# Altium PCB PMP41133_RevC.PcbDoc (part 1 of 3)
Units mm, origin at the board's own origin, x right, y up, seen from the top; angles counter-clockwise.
Board outline 150 x 82 mm, 4 copper layers (Top Layer, Int1 (GND), Int2 (PWR), Bottom Layer), stack 1.369 mm thick; 186 components, 74 nets, 388 pads, 329 vias.
Unrouted connection lines stored in the file: 2.
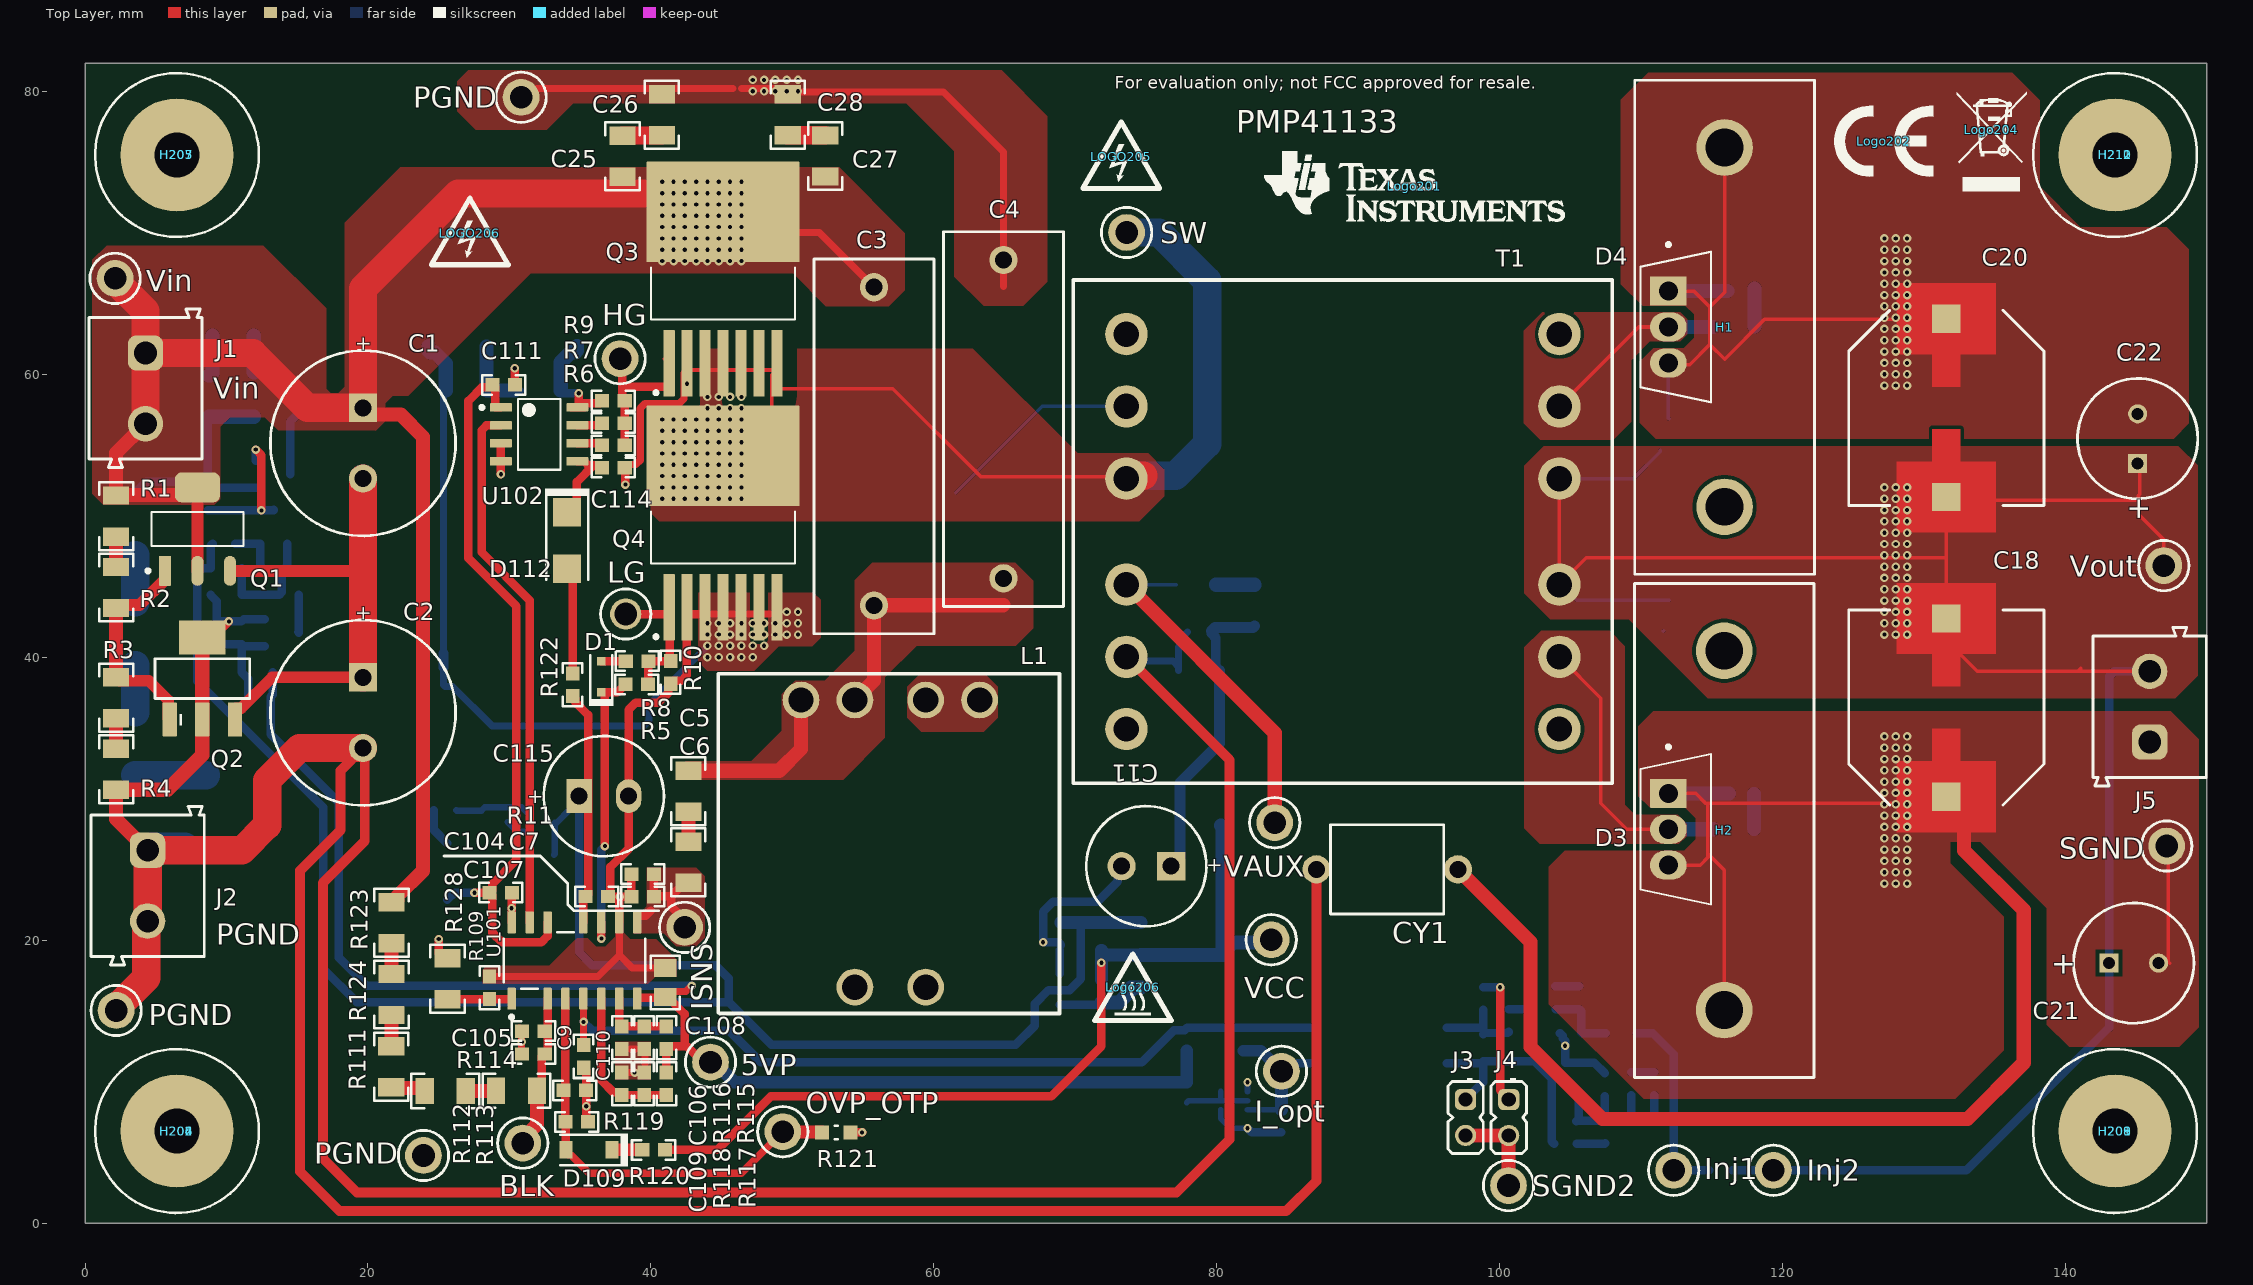
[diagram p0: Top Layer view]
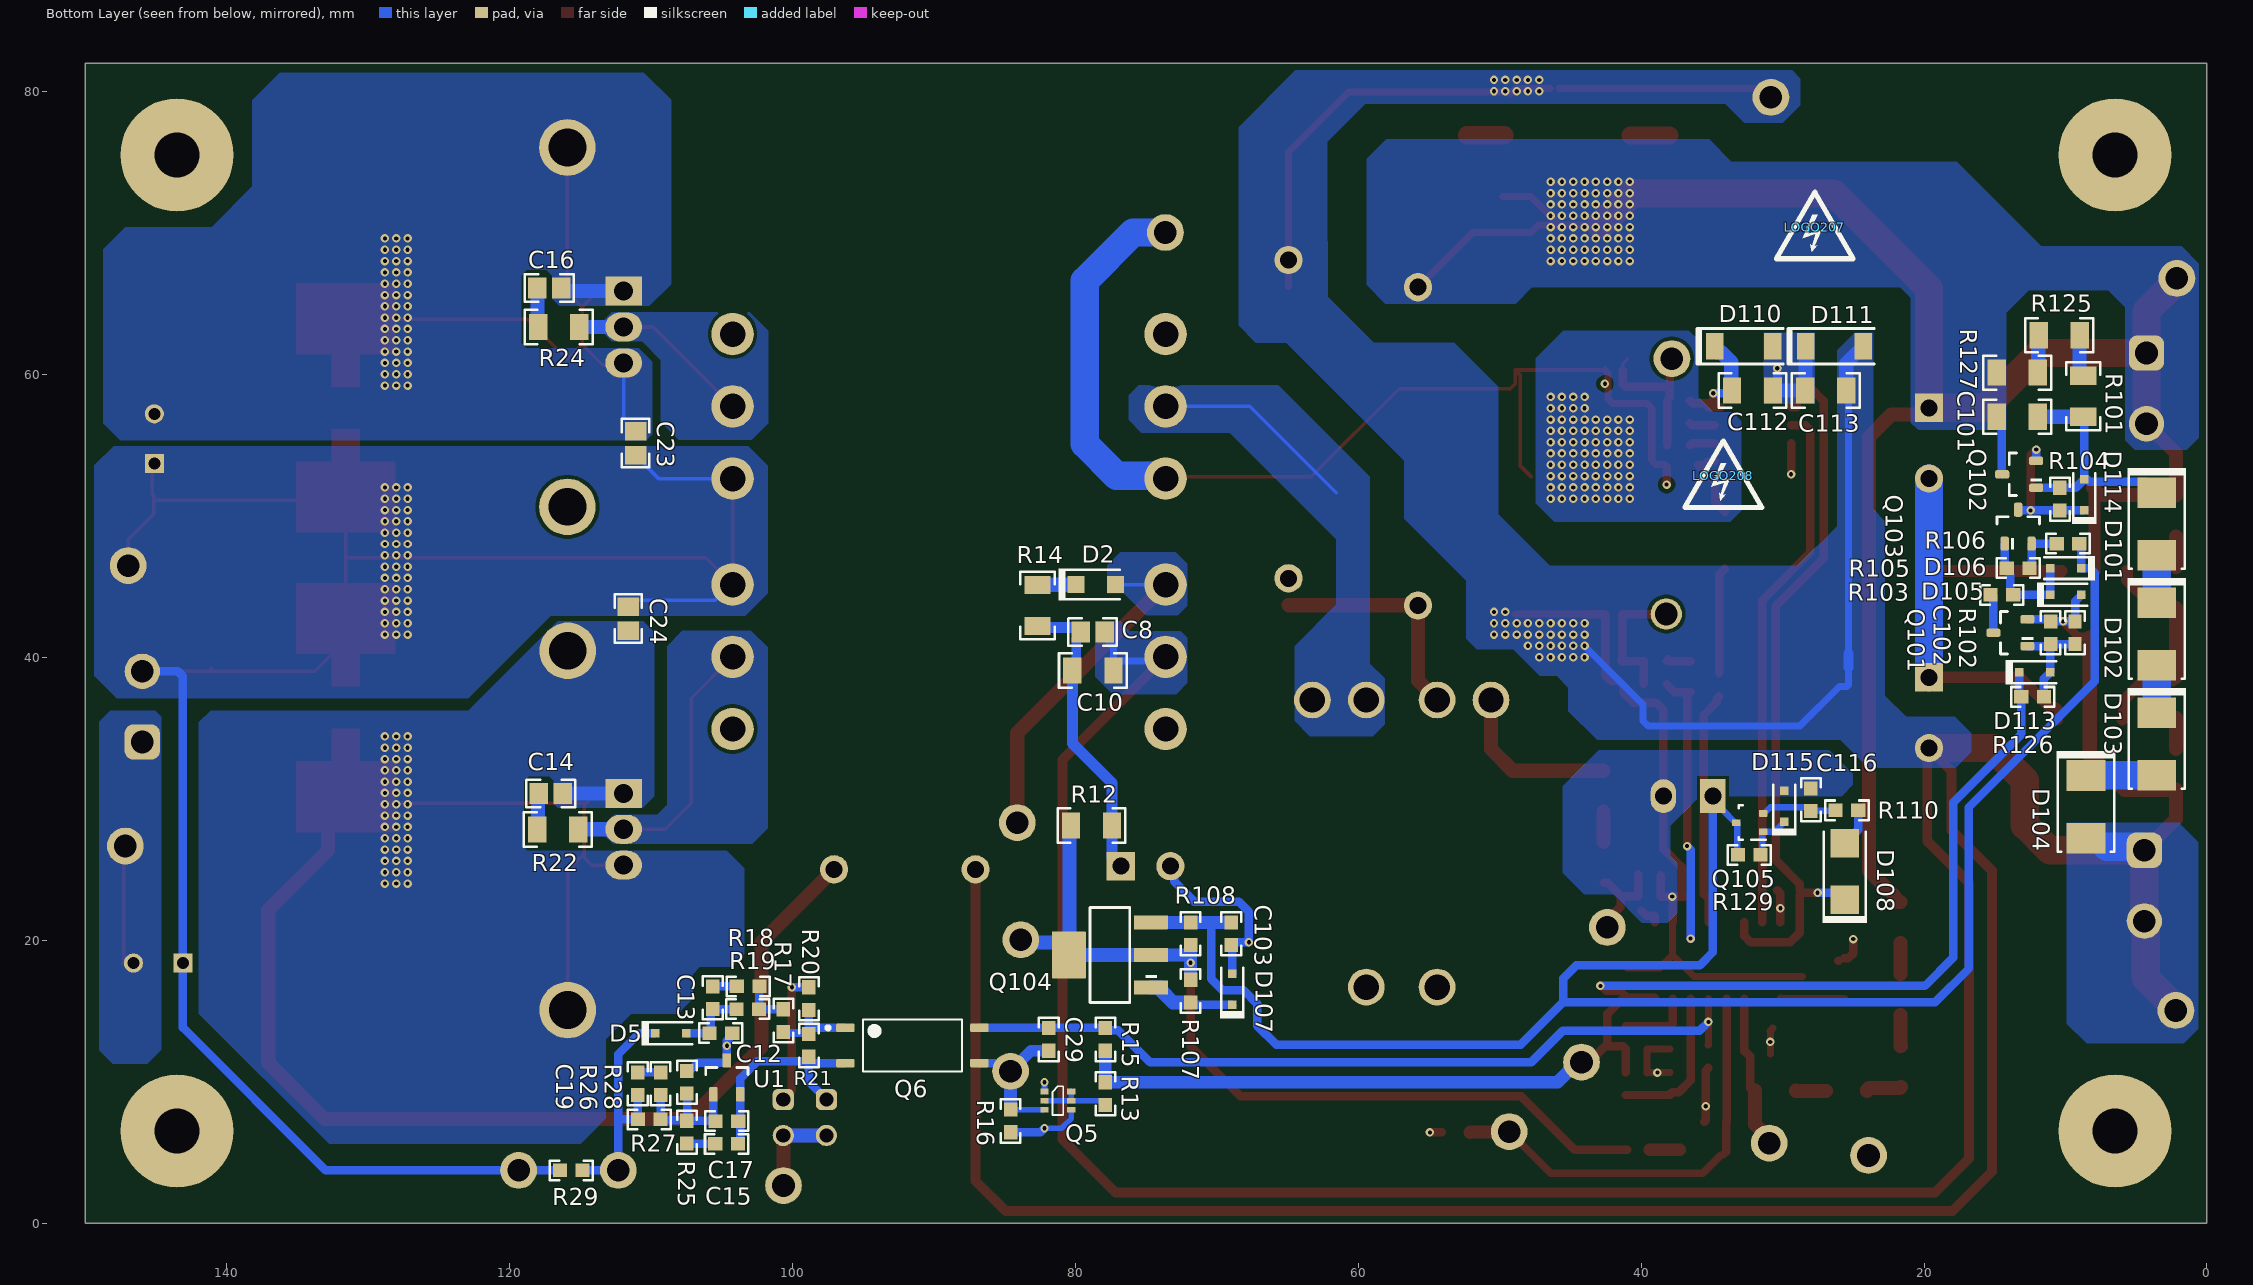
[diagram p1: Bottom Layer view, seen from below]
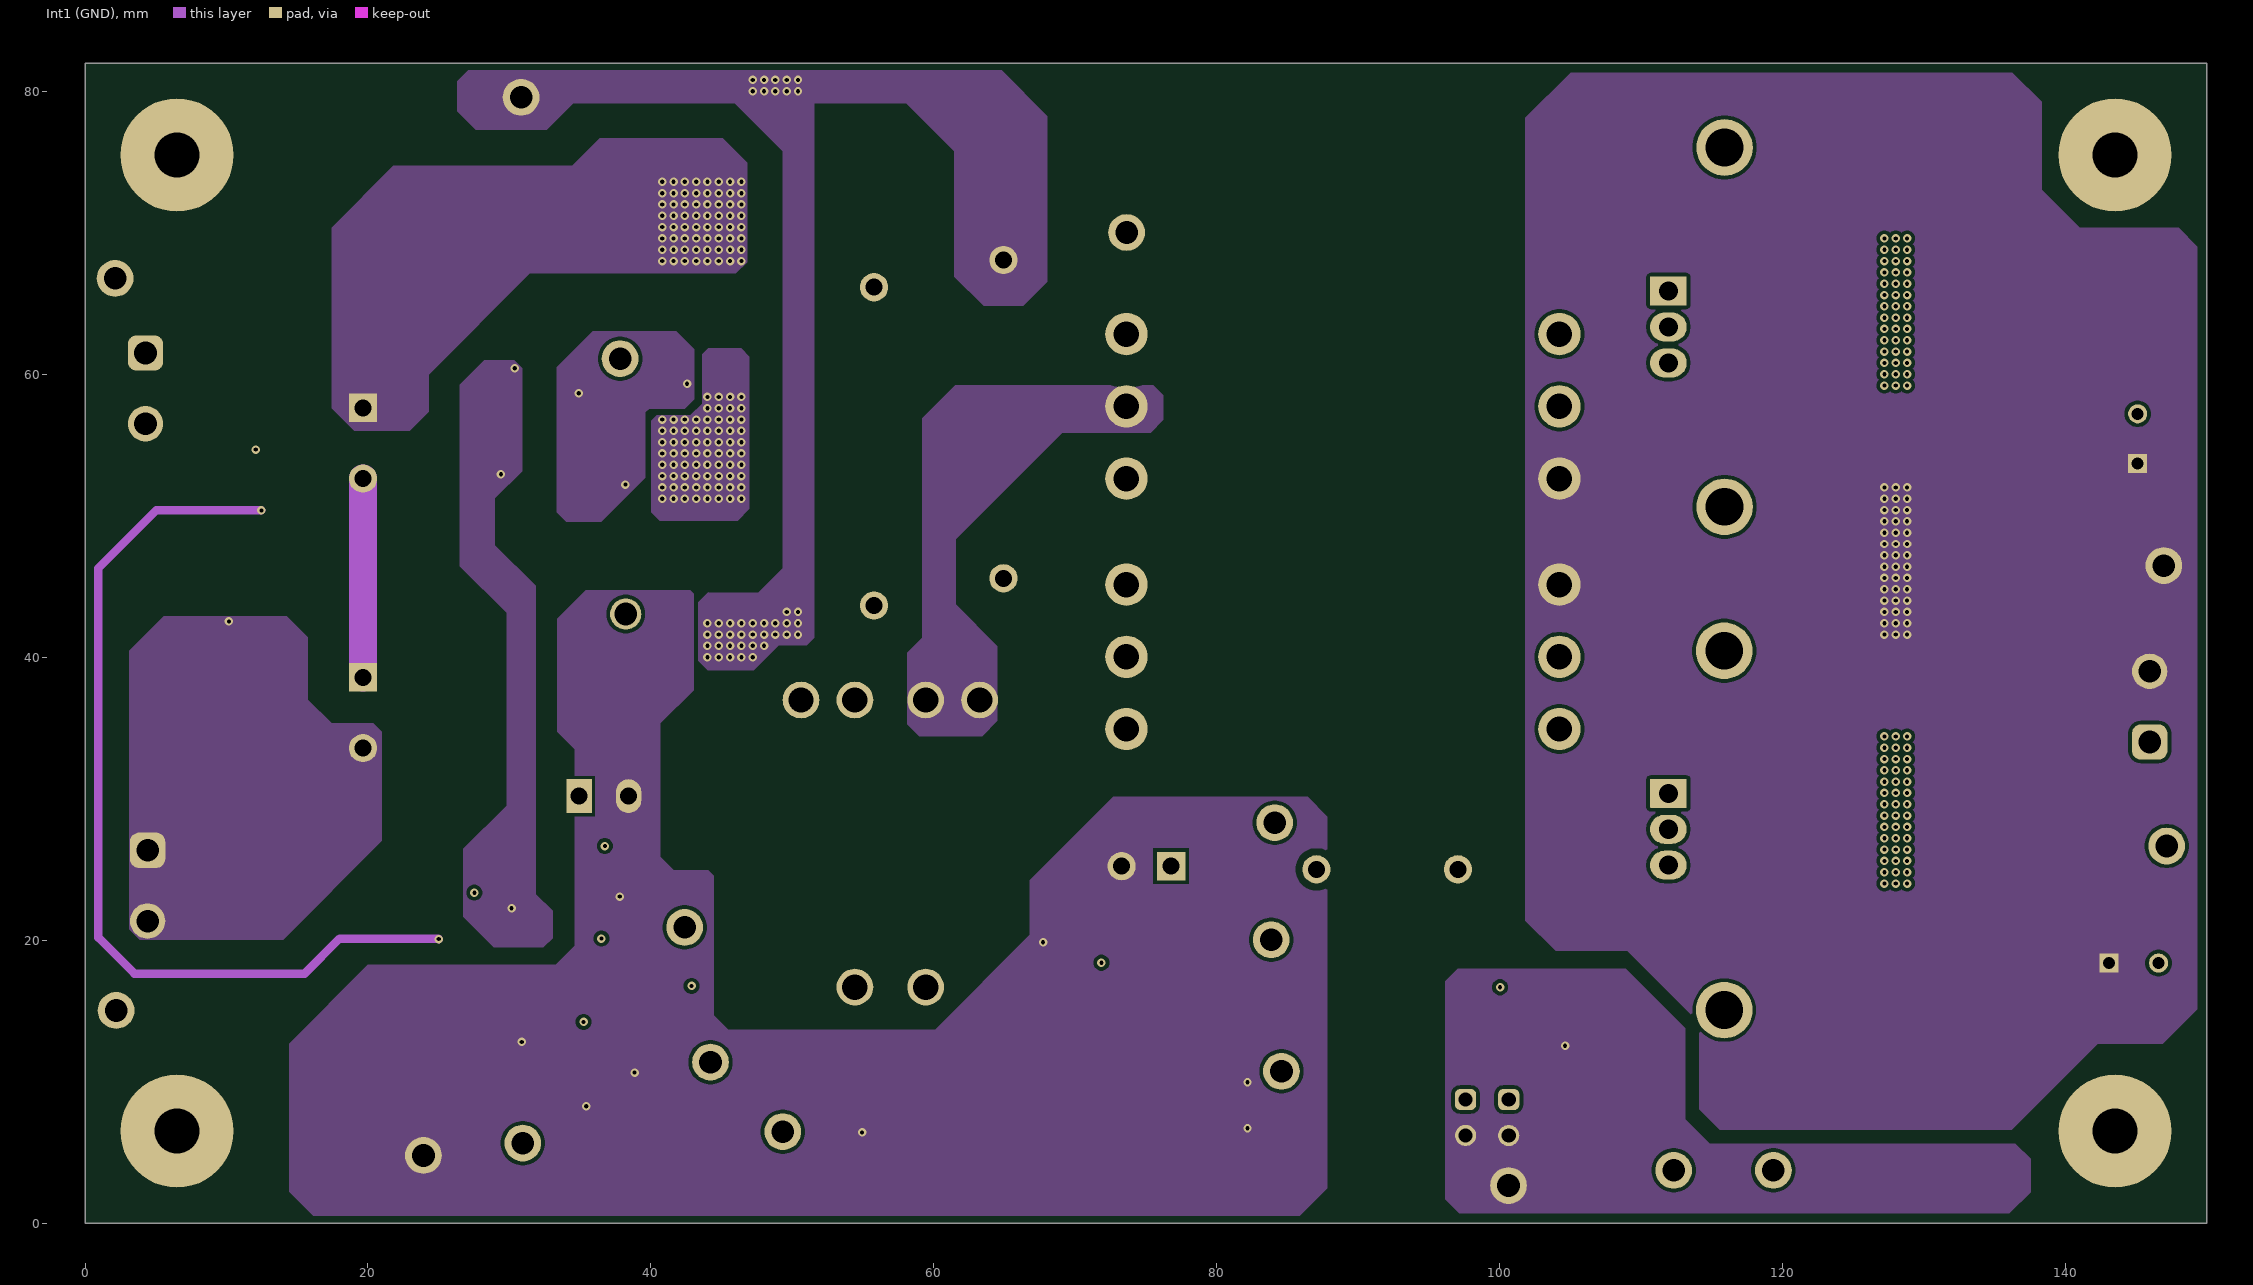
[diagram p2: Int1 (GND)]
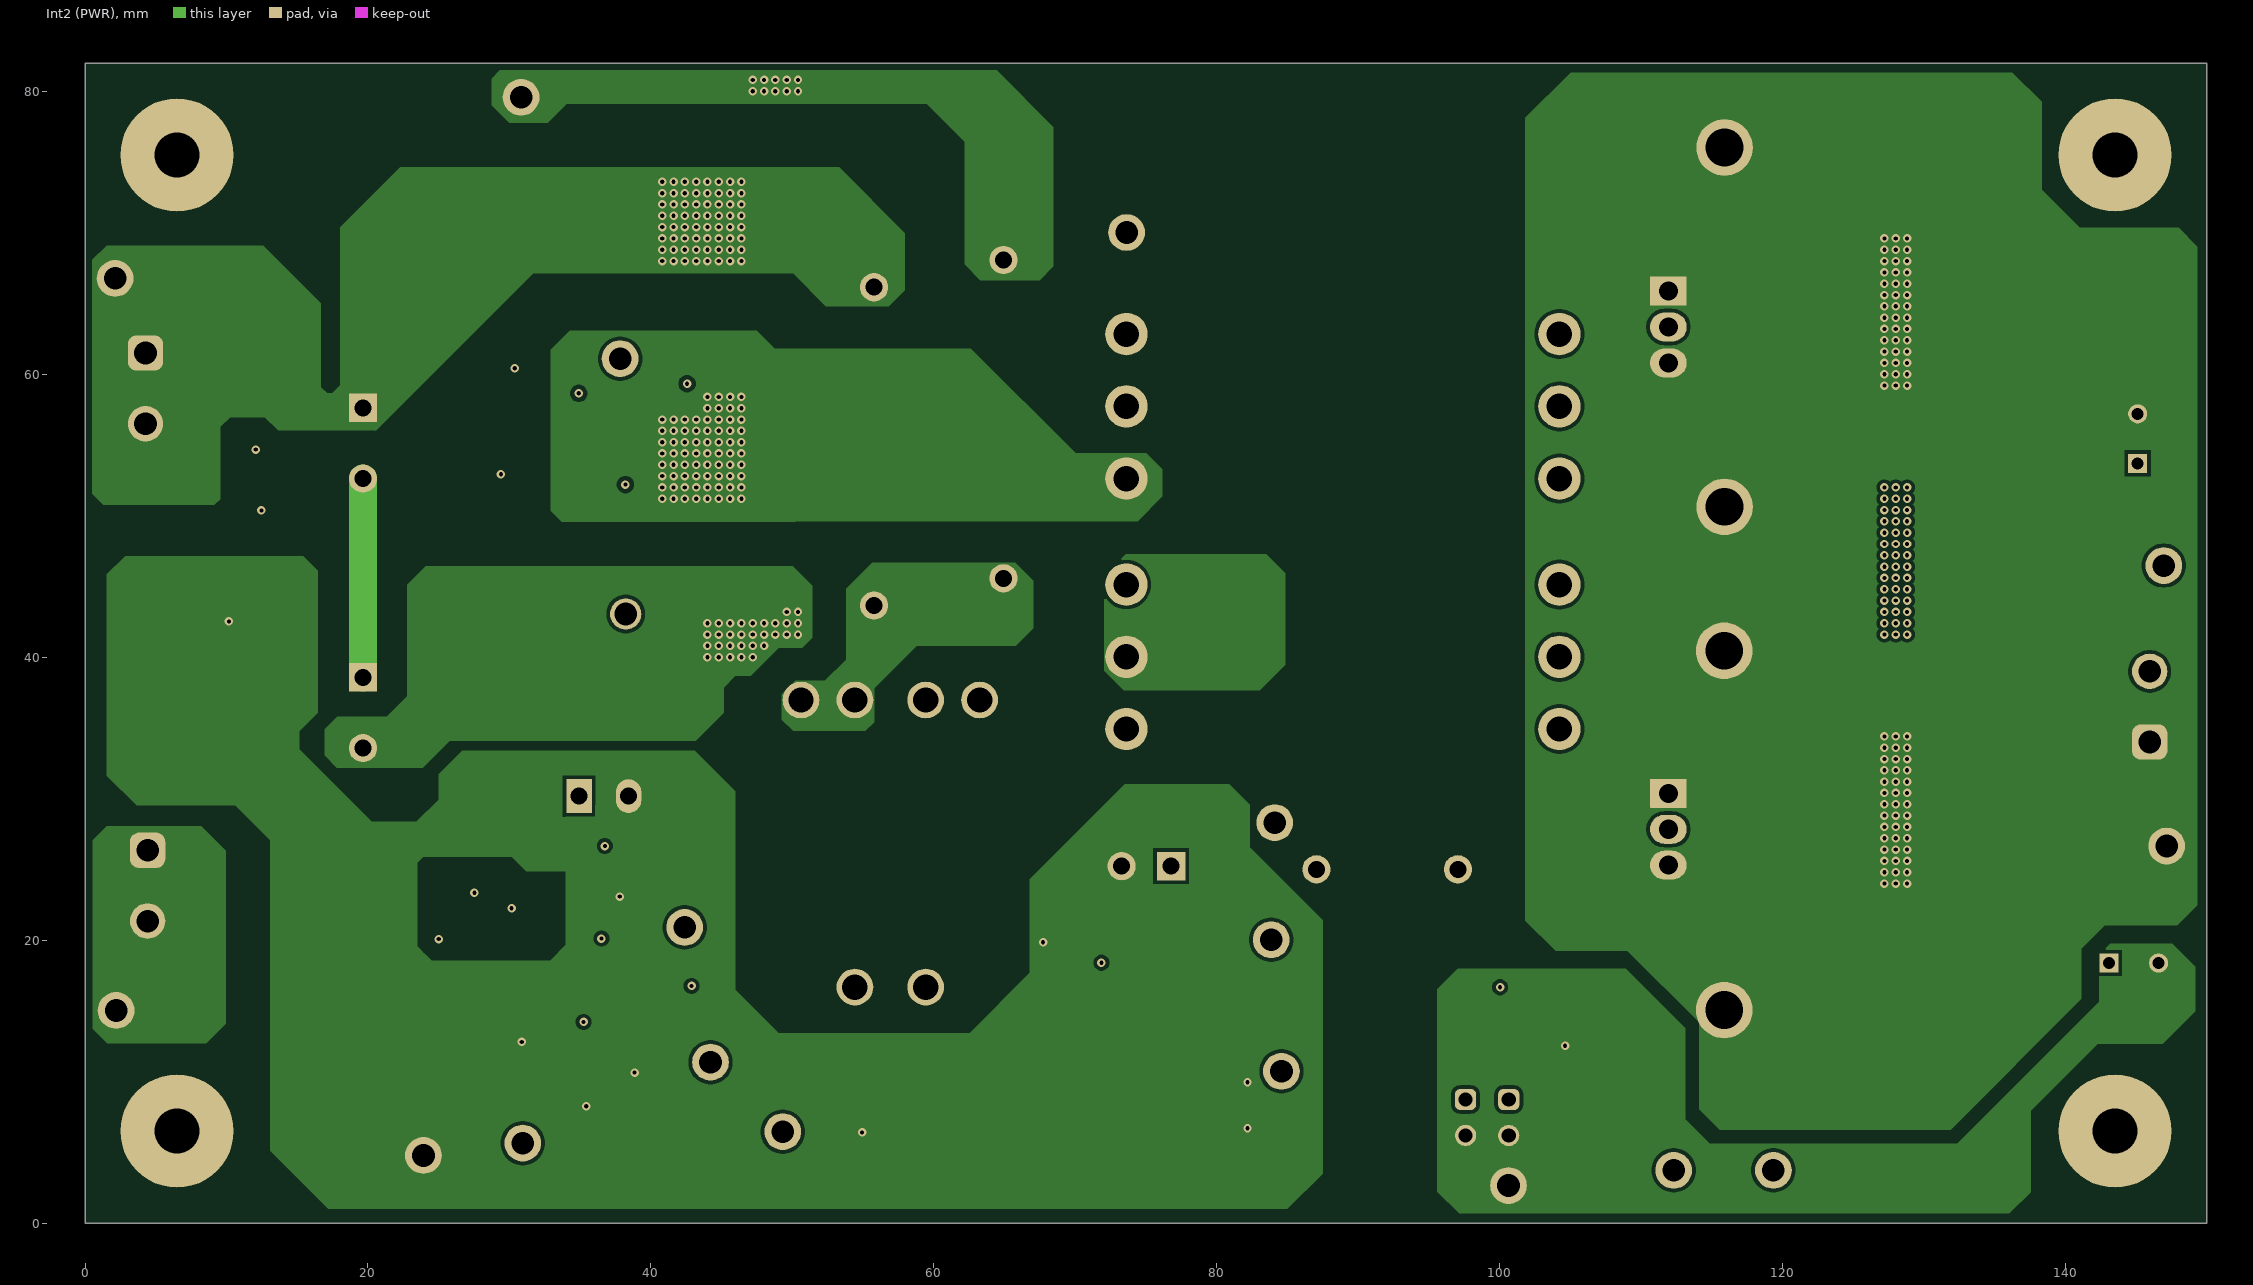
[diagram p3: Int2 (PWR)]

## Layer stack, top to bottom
Top Solder: solder mask 0.0254, SM-001, Dk 4
Top Layer: signal copper 0.035
Dielectric 1: prepreg 0.1295, PP-017, Dk 4.3
Dielectric 2: prepreg 0.1295, PP-017, Dk 4.3
Int1 (GND): signal copper 0.035
Dielectric 3: core 0.7112, Core-039, Dk 4.8
Int2 (PWR): signal copper 0.035
Dielectric 4: prepreg 0.1295, PP-017, Dk 4.3
Dielectric 5: prepreg 0.1295, PP-017, Dk 4.3
Bottom Layer: signal copper 0.035
Bottom Solder: solder mask 0.0254, SM-001, Dk 4

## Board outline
0,0 150,0 150,82 0,82

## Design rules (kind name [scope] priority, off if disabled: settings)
AcuteAngle [All] p1: minimum=4.50000000000000E+0001 checktracksonly=FALSE
AssemblyTestPointUsage [All] p1: valid=2
BoardOutlineClearance BoardOutlineClearance_MountingHoles [OnCopper and InComponentClass('Mounting Holes')] p1: gap=0.5 ignorepadtopadclearanceinfootprint=FALSE
BoardOutlineClearance BoardOutlineClearance_Poly [OnCopper and IsPoly] p2: gap=0.5 ignorepadtopadclearanceinfootprint=FALSE
BoardOutlineClearance [OnCopper and Not InComponentClass('Logo') and not InComponentClass('FiducialMark') and not InRegion(1000,500,4000,800) and not InPoly] p3: gap=0.5 ignorepadtopadclearanceinfootprint=FALSE
Clearance Clearance_3 [InNetClass('HV') vs InNetClass('MV')] p1: gap=1.14 ignorepadtopadclearanceinfootprint=TRUE
Clearance Clearance_4 [InNetClass('All Nets') vs InNet('No Net')] p2: gap=0.5 ignorepadtopadclearanceinfootprint=TRUE
Clearance Clearance_2 [InNetClass('HV') vs Not InNetClass('HV')] p3: gap=2.28 ignorepadtopadclearanceinfootprint=TRUE
Clearance Clearance_1 [InNetClass('MV') vs Not InNetClass('MV')] p4: gap=1.14 ignorepadtopadclearanceinfootprint=TRUE
Clearance Clearance_Keepouts [((IsTrack Or IsArc) And Not InPoly) And IsFree and IsKeepOut vs ((IsTrack Or IsArc) And Not InPoly) And IsFree and IsKeepOut] p5: gap=0 ignorepadtopadclearanceinfootprint=FALSE
Clearance Clearance_Poly [InPolygon] p6: gap=0.25 ignorepadtopadclearanceinfootprint=TRUE
Clearance Clearance_FiducialMark [IsKeepOut and InComponentClass('FiducialMark') vs IsPad and InComponentClass('FiducialMark')] p7: gap=0 ignorepadtopadclearanceinfootprint=FALSE
Clearance [All] p8: gap=0.25 ignorepadtopadclearanceinfootprint=TRUE
ComponentClearance ComponentClearance_MountingHoles_FiducialMarks [InComponentClass('Mounting Holes') vs InComponentClass('FiducialMark')] p1: gap=1.27 collisioncheckmode=3 verticalgap=0.254 showdistances=FALSE
ComponentClearance ComponentClearance_Shunt [InComponentClass('Header') vs InComponentClass('Shunt')] p2: gap=0 collisioncheckmode=3 verticalgap=0 showdistances=FALSE
ComponentClearance ComponentClearance_Logo [InComponentClass('Logo')] p3: gap=0.762 collisioncheckmode=3 verticalgap=0.254 showdistances=FALSE
ComponentClearance ComponentClearance_ScrewToNut [(HasFootprint('NY PMS 440 0025 PH')) vs (HasFootprint('Keystone_1902C'))] p4: gap=0.127 collisioncheckmode=3 verticalgap=0.254 showdistances=FALSE
ComponentClearance ComponentClearance_MountingHoles [InComponentClass('Mounting Holes')] p5: gap=2.54 collisioncheckmode=3 verticalgap=2540 showdistances=FALSE
ComponentClearance ComponentClearance_SmallPassives [HasFootprint('0201*') or HasFootprint('0402*') or HasFootprint('0508') or HasFootprint('0603*') or HasFootprint('0612') or HasFootprint('0805*') or HasFootprint('0815*') or HasFootprint('0830*') or HasFootprint('1206*') or HasFootprint('1210*') or HasFootprint('1808*') or HasFootprint('1812*') or HasFootprint('1825*') or HasFootprint('2010*') or HasFootprint('2220*') or HasFootprint('2225*') or HasFootprint('2512*') or HasFootprint('2728*') or HasFootprint('3518*') vs HasFootprint('0201*') or HasFootprint('0402*') or HasFootprint('0508') or HasFootprint('0603*') or HasFootprint('0612') or HasFootprint('0805*') or HasFootprint('0815*') or HasFootprint('0830*') or HasFootprint('1206*') or HasFootprint('1210*') or HasFootprint('1808*') or HasFootprint('1812*') or HasFootprint('1825*') or HasFootprint('2010*') or HasFootprint('2220*') or HasFootprint('2225*') or HasFootprint('2512*') or HasFootprint('2728*') or HasFootprint('3518*')] p6: gap=0.38 collisioncheckmode=3 verticalgap=0.254 showdistances=FALSE
ComponentClearance ComponentClearance_THtoSMT [IsThruComponent vs IsSMTComponent] p7: gap=0.762 collisioncheckmode=3 verticalgap=0.762 showdistances=FALSE
ComponentClearance ComponentClearance_THtoTH [IsThruComponent vs IsThruComponent] p8: gap=0.508 collisioncheckmode=3 verticalgap=0.762 showdistances=FALSE
ComponentClearance [All] p9: gap=0.508 collisioncheckmode=3 verticalgap=0.254 showdistances=FALSE
DiffPairsRouting [All] p1: maxlimit=2.54 minlimit=0.254 mostfreqgap=0.254 toplayer_minwidth=0.381 toplayer_maxwidth=0.381 toplayer_prefwidth=0.381 midlayer1_minwidth=0.381 midlayer1_maxwidth=0.381 midlayer1_prefwidth=0.381 midlayer2_minwidth=0.381 midlayer2_maxwidth=0.381 midlayer2_prefwidth=0.381 bottomlayer_minwidth=0.381 bottomlayer_maxwidth=0.381 bottomlayer_prefwidth=0.381 maxuncoupledlength=25.4
FabricationTestPointUsage TestPointUsage [All] p1: valid=2 allowmultiple=FALSE
FabricationTestpoint Testpoint [All] p1: side=3 testpointundercomponent=TRUE minsize=1.016 maxsize=2.54 preferedsize=1.524 minholesize=0 maxholesize=1.016 preferedholesize=0.813 testpointgrid=0.025 allowsidetop=TRUE allowsidebottom=TRUE usegrid=TRUE gridtolerance=0
FanoutControl Fanout_LCC [IsLCC] p1: bgadir=Out bgaviamode=Centered fanoutstyle=Auto fanoutdirection=Alternating viagrid=0.025 // Fanout_LCC (Default Rule)
FanoutControl Fanout_BGA [IsBGA] p2: bgadir=Out bgaviamode=Centered fanoutstyle=Auto fanoutdirection=Alternating viagrid=0.025 // Fanout_BGA (Default Rule)
FanoutControl Fanout_Default [All] p4: bgadir=Out bgaviamode=Centered fanoutstyle=Auto fanoutdirection=Alternating viagrid=0.025 // Fanout_Default (Default Rule)
FanoutControl Fanout_Small [(CompPinCount < 5)] p5: bgadir=Out bgaviamode=Centered fanoutstyle=Auto fanoutdirection=OutThenIn viagrid=0.025 // Fanout_Small (Default Rule)
Height [All] p1: minheight=0 maxheight=127 prefheight=12.7
HoleSize [All] p1: absolutevalues=TRUE maxlimit=6.375 minlimit=0.2 maxpercent=80.000 minpercent=20.000
MinimumAnnularRing MinimumAnnularRing_ThermalPadVias [IsVia and InAnyComponent] p1: minimumring=0.15
MinimumAnnularRing [All] p2: minimumring=0.2
MinimumSolderMaskSliver MinimumSolderMaskSliver_Logo [InComponentClass('Logo') vs InComponentClass('Logo')] p1: minsoldermaskwidth=0.018
MinimumSolderMaskSliver [All] p2: minsoldermaskwidth=0.1
PlaneConnect [All] p1: planeconnectstyle=Direct reliefexpansion=0.254 reliefentries=4 reliefconductorwidth=0.254 reliefairgap=0.254
PolygonConnect [All] p1: connectstyle=Direct reliefconductorwidth=0.254 reliefentries=4 polygonreliefangle="90 Angle" airgapwidth=0.254
RoutingVias ThermalPadVias [IsVia and InAnyComponent] p1: holewidth=0.3 width=0.6 viastyle="Through Hole" minholewidth=0.2 minwidth=0.5 maxholewidth=0.33 maxwidth=0.6
RoutingVias [All] p2: holewidth=0.3 width=0.6 viastyle="Through Hole" minholewidth=0.2 minwidth=0.61 maxholewidth=1.016 maxwidth=1.651
SilkToBoardRegionClearance [Not ((IsComment or IsDesignator) And (Hide <> 'False')) and not InRegion(1000,500,4000,800)] p1:
SilkToSilkClearance SilkToSilkClearance_Pb-FreeLogo [(HasFootprint('Pb-Free_Overlay_Medium') OR HasFootprint('Pb-Free_Overlay_Small')) vs (HasFootprint('Pb-Free_Overlay_Medium') OR HasFootprint('Pb-Free_Overlay_Small'))] p1: silktosilkclearance=0
SilkToSilkClearance [All] p2: silktosilkclearance=0.1
SilkToSolderMaskClearance SilkToComponentPadClearance [(IsPad or IsFill or IsRegion) and InAnycomponent] p1: minsilkscreentomaskgap=0.127 clearancetoexposedcopper=TRUE
SilkToSolderMaskClearance "Silk to Solder Mask Opening" [All] p2: minsilkscreentomaskgap=0.1 clearancetoexposedcopper=FALSE
SolderMaskExpansion [All] p1: expansion=0.05 istentingtop=FALSE
UnRoutedNet [All] p1: checkbadconnections=TRUE
Width [All] p1: maxlimit=2.54 minlimit=0.152 preferedwidth=0.508 minimp=50.000000 maximp=50.000000 favimp=50.000000 checkconnectedcopper=TRUE
13 further rules are at their usual default settings.

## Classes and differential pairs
net class HV: HO HO_OFF HS NetC3_2 NetC114_2 NetHG_1 NetL1_2 VIN
component class PMP41133_REVC_Hardware: !PCB H201 H202 H203 H204 H205 H206 H207 H208 H209 H210 H211 H212 Logo201 Logo202 Logo203 Logo204 LOGO205 Logo206
component class "PMP41133_RevC_Power Stage": C1 C2 C3 C4 C5 C6 C7 C8 C9 C10 C11 C12 C13 C14 C15 C16 C17 C18 C19 C20 C21 C22 C23 C24 C25 C26 C27 C28 C29 CY1 D1 D2 D3 D4 D5 H1 H2 HG I_opt Inj1 Inj2 Inj+ Inj- ISNS J1 J2 J3 J4 J5 L1 LG PGND Q1 Q2 Q3 Q4 Q5 Q6 R1 R2 R3 R4 R5 R6 R7 R8 R9 R10 R11 R12 R13 R14 R15 R16 R17 R18 R19 R20 R21 R22 R24 R25 R26 R27 R28 R29 SGND SGND2 SW T1 U1 VAUX VCC Vin Vout
component class "Mounting Holes": H203 H206 H209 H212
component class Logo: Logo201
component class Header: J3 J4
net class MV: HB HO_CTRL HS_CTRL NetC1_2 NetC5_2 NetC25_2 NetC27_2 NetC101_1 NetD101_2 NetD102_2 NetD103_2 NetD114_1 NetQ1_1 NetR1_1 NetR3_1 NetR101_2 NetR111_1 NetR111_2 NetR112_1 NetR123_1 NetR125_2
component class PMP41133_RevC_Controller: 5VP BLK C101 C102 C103 C104 C105 C106 C107 C108 C109 C110 C111 C112 C113 C114 C115 C116 D101 D102 D103 D104 D105 D106 D107 D108 D109 D110 D111 D112 D113 D114 D115 OVP_OTP Q101 Q102 Q103 Q104 Q105 R101 R102 R103 R104 R105 R106 R107 R108 R109 R110 R111 R112 R113 R114 R115 R116 R117 R118 R119 R120 R121 R122 R123 R124 R125 R126 R127 R128 R129 U101 U102

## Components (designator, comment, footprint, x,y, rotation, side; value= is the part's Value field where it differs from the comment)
5VP "5010" Keystone5010 44.214,11.373 r90 top
BLK "5012" Keystone5012#1 30.944,5.65 r0 top
C1 "UCY2H220MHD" UCY_1250x3550 19.65,55.125 r270 top locked value=22uF
C2 "UCY2H220MHD" UCY_1250x3550 19.65,36.075 r270 top locked value=22uF
C3 "B81123C1682M" B81123_2650x850x1650 55.775,54.9 r270 top value=6800pF
C4 "B81123C1682M" B81123_2650x850x1650 64.925,56.825 r90 top value=6800pF
C5 "VJ1206A101JXGAT5Z" 1206 42.65,30.525 r270 top value=100pF
C6 "VJ1206A101JXGAT5Z" 1206 42.65,25.5 r270 top value=100pF
C7 "C0603C221K5GACTU" 0603 39.425,23.075 r180 top value=220pF
C8 "C2012X7R1V225K085AC" 0805 78.775,41.775 r180 bottom value=2.2uF
C9 "GRM188R71H332KA01D" 0603 35.25,11.775 r270 top value=3300pF
C10 "GRM31CR71E106MA12L" 1206 78.75,39.05 r180 bottom value=10uF
C11 "ECA-1VM221BJ" M_800x1150#1 75.025,25.225 r180 top locked value=220uF
C12 "C0603C101J5GACTU" 0603 105.05,13.425 r180 bottom value=100pF
C13 "GCM188R72A472KA37D" 0603 105.625,15.925 r90 bottom value=4700pF
C14 "GRM2165C2A471JA01D" 0805 117.076,30.365 r180 bottom value=470pF
C15 "GRM188R71H103KA01D" 0603 104.65,5.6 r0 bottom value=0.01uF
C16 "GRM2165C2A471JA01D" 0805 117.183,66.1 r180 bottom value=470pF
C17 "GRM1885C1H151JA01D" 0603 104.625,7.2 r180 bottom value=150pF
C18 "A783MW187M1JLASO15" UCZ_1250x1350 131.575,36.44 r90 top locked value=180uF
C19 "GRM188R72A471KA01D" 0603 110.925,9.85 r90 bottom value=470pF
C20 "A783MW187M1JLASO15" UCZ_1250x1350 131.575,57.625 r270 top locked value=180uF
C21 "UPJ1K470MPD1TD" PJ_800X1500 144.825,18.375 r0 top value=47uF
C22 "UPJ1K470MPD1TD" PJ_800X1500 145.1,55.45 r90 top value=47uF
C23 "C2012X7S2A474K125AB" 0805 111.075,55.125 r270 bottom locked value=0.47uF
C24 "C2012X7S2A474K125AB" 0805 111.6,42.725 r90 bottom value=0.47uF
C25 "VJ1206Y223KXGAT5Z" 1206 38,75.4 r90 top value=0.022uF
C26 "VJ1206Y223KXGAT5Z" 1206 40.775,78.35 r90 top value=0.022uF
C27 "VJ1206Y223KXGAT5Z" 1206 52.325,75.425 r90 top value=0.022uF
C28 "VJ1206Y223KXGAT5Z" 1206 49.675,78.35 r90 top value=0.022uF
C29 "C0603C104K5RACAUTO" 0603 81.875,12.975 r270 bottom value=0.1uF
C101 "VJ1206A100JXGAT5Z" 1206 13.4,56.995 r0 bottom value=10pF
C102 "GRM188R6YA106MA73" 0603 11.057,41.725 r90 bottom value=10uF
C103 "CGA3E1X7R1E105K080AC" 0603 68.975,20.45 r270 bottom value=1uF
C104 "CGA3E1X7R1E105K080AC" 0603 36.175,23.082 r0 top value=1uF
C105 "GRM188R71H103KA01D" 0603 31.7,13.57 r180 top value=0.01uF
C106 "C0603X221K5RACTU" 0603 37.95,13.1 r270 top value=220pF
C107 "C0603C104K5RACTU" 0603 29.394,23.35 r0 top value=0.1uF
C108 "GRM21BR71E475KA73L" 0805_HV 41.012,17.007 r90 top value=4.7uF
C109 "C0603X102K5RACTU" 0603 37.95,9.85 r90 top value=1000pF
C110 "C0603X222K5RACTU" 0603 34.625,9.374 r0 top value=2200pF
C111 "GCM188R71E104KA57D" 0603 29.6,59.25 r0 top value=0.1uF
C112 "GRM31A7U3A680JW31D" 1206 32.125,58.85 r180 bottom value=68pF
C113 "GRM31A7U3A680JW31D" 1206 26.95,58.85 r180 bottom value=68pF
C114 "C0603C104K5RACTU" 0603 37.35,53.4 r180 top value=0.1uF
C115 "ECA-1VM221BJ" M_800x1150#2 36.675,30.175 r0 top value=220uF
C116 "CGA3E1X7R1E105K080AC" 0603 28,29.925 r90 bottom value=1uF
CY1 "DE1B3KX221KA4BN01F" DE1_800x700x1100 92.05,25 r180 top value=220pF
D1 "1N4148WS-7-F" SOD-323 36.503,38.609 r90 top value=75V
D2 "PMEG10020ELRX" SOD-123W 78.55,45.132 r180 bottom value=100V
D3 "DSA30I150PA" FP-MBR30200CTE3_TU_TO220-3-MFG 112.439,27.835 r0 top
D4 "DSA30I150PA" FP-MBR30200CTE3_TU_TO220-3-MFG 112.439,63.34 r0 top locked
D5 "SZMM3Z18VST1G" SOD-323 108.6,13.425 r180 bottom value=18V
D101 "1SMB5952BT3G" SMB 3.55,49.425 r270 bottom value=130V
D102 "1SMB5952BT3G" SMB 3.55,41.65 r270 bottom value=130V
D103 "1SMB5952BT3G" SMB 3.55,33.875 r270 bottom value=130V
D104 "1SMB5952BT3G" SMB 8.55,29.425 r270 bottom value=130V
D105 "SZMM3Z18VST1G" SOD-323 9.975,44.4 r180 bottom value=18V
D106 "SZMM3Z18VST1G" SOD-323 9.975,46.3 r0 bottom value=18V
D107 "SZMM3Z18VST1G" SOD-323 68.9,16.525 r90 bottom value=18V
D108 "STTH1R06A" SMA 25.6,24.85 r90 bottom value=600V
D109 "DDZ26Q-7" SOD-123 35.625,5.175 r180 top value=26V
D110 "ES1JAF" SMAF 32.75,61.975 r180 bottom value=600V
D111 "ES1JAF" SMAF 26.325,61.975 r180 bottom value=600V
D112 "STTH112A" SMA 34.075,48.25 r270 top value=1200V
D113 "XBS104S13R-G" SOD-323 12.175,38.925 r180 bottom value=40V
D114 "MM3Z12VST1G" SOD-323 8.675,51.475 r90 bottom value=12V
D115 "MM3Z15VST1G" SOD-323 29.875,29.45 r90 bottom value=15V
H1 "531202B02500G" 531202 115.9,63.325 r270 top
H2 "531202B02500G" 531202 115.875,27.75 r270 top locked
H201 "SJ-5303 (CLEAR)" Bumpon_SJ5003Transparent 143.5,6.5 r0 top
H202 "1902C" Keystone_1902C 6.5,6.5 r0 top
H203 "NY PMS 440 0025 PH" "NY PMS 440 0025 PH" 6.5,75.5 r0 top
H204 "SJ-5303 (CLEAR)" Bumpon_SJ5003Transparent 6.5,6.5 r0 top
H205 "1902C" Keystone_1902C 6.5,75.5 r0 top
H206 "NY PMS 440 0025 PH" "NY PMS 440 0025 PH" 6.5,6.5 r0 top
H207 "SJ-5303 (CLEAR)" Bumpon_SJ5003Transparent 6.5,75.5 r0 top
H208 "1902C" Keystone_1902C 143.5,6.5 r0 top
H209 "NY PMS 440 0025 PH" "NY PMS 440 0025 PH" 143.5,6.5 r0 top
H210 "SJ-5303 (CLEAR)" Bumpon_SJ5003Transparent 143.5,75.5 r0 top
H211 "1902C" Keystone_1902C 143.5,75.5 r0 top
H212 "NY PMS 440 0025 PH" "NY PMS 440 0025 PH" 143.5,75.5 r0 top
HG "5012" Keystone5012#1 37.825,61.1 r0 top
I_opt "5012" Keystone5012#1 84.575,10.725 r90 top
Inj1 "5013" Keystone5013 112.3,3.725 r0 top
Inj2 "5013" Keystone5013 119.35,3.725 r0 top
ISNS "5012" Keystone5012#1 42.388,20.898 r90 top
J1 "691111710002" 691111710002 4.275,59 r270 top locked
J2 "691111710002" 691111710002 4.425,23.844 r270 top locked
J3 "961102-6804-AR" 3M_961102-68 97.593,7.461 r270 top
J4 "961102-6804-AR" 3M_961102-68 100.64,7.456 r270 top
J5 "691111710002" 691111710002 145.95,36.5 r90 top
L1 "750345698" "Inductor 750345698" 56.925,26.825 r270 top locked
LG "5012" Keystone5012#2 38.223,43.05 r0 top
Logo201 "Texas Instruments" TI_Stacked_Overlay_Small 93.975,73.275 r0 top
Logo202 "CE Mark" CE_Mark_5mm 127.15,76.475 r0 top
Logo203 "FCC disclaimer" FCC_disclaimer 156.225,15.625 r90 top
Logo204 "WEEE logo" WEEE_Minimum 134.75,77.3 r0 top
LOGO205 "DANGER HIGH VOLTAGE" IEC_HighVoltage_Small 73.25,75.362 r0 top
LOGO206 "DANGER HIGH VOLTAGE" IEC_HighVoltage_Small 27.2,69.975 r0 top (schematic designator LOGO205)
Logo206 "CAUTION HOT SURFACE" IEC_HotSurface_Small 74.075,16.678 r0 top
LOGO207 "DANGER HIGH VOLTAGE" IEC_HighVoltage_Small 27.725,70.4 r180 bottom (schematic designator LOGO205)
LOGO208 "DANGER HIGH VOLTAGE" IEC_HighVoltage_Small 34.19,52.825 r180 bottom (schematic designator LOGO205)
OVP_OTP "5012" Keystone5012#1 49.325,6.457 r90 top
PGND "5011" Keystone5011 23.925,4.775 r0 top
PGND "5011" Keystone5011 30.825,79.575 r0 top
PGND "5011" Keystone5011 2.2,15.025 r0 top
Q1 "PBHV8560Z" FP-PBHV8560Z_SOT-223-IPC_B 7.95,49.05 r90 top value=600V
Q2 "PBHV9050Z,115" SOT-223 8.29,38.486 r90 top value="500 V"
Q3 "IMBG120R234M2HXTMA1" FP-IMBG120R026M2HXTMA1_TO263-7-MFG 45.1,68.6 r0 top locked
Q4 "IMBG120R234M2HXTMA1" FP-IMBG120R026M2HXTMA1_TO263-7-MFG 45.1,51.35 r0 top locked
Q5 "MMDT3904-7-F" SOT-363 81.225,8.65 r180 bottom value="40 V"
Q6 "ISOM8110DFSR" DFS0004A-MFG 91.517,12.55 r180 bottom value=80V
Q101 "2N7002Q-7-F" SOT-23 13.9,41.725 r0 bottom value=60V
Q102 "BSS126H6327XTSA2" SOT-23 13.275,52.925 r0 bottom value=600V
Q103 "BSS126H6327XTSA2" SOT-23 13.35,49.225 r90 bottom value=600V
Q104 "FZT651TA" SOT-223 77.55,18.95 r0 bottom value="60 V"
Q105 "2N7002W-7-F" SOT-323 32.325,28.3 r0 bottom value=60V
R1 "RC1206FR-071ML" 1206 2.2,49.975 r90 top value=1.00Meg
R2 "RC1206FR-071ML" 1206 2.2,44.925 r90 top value=1.00Meg
R3 "RC1206FR-071ML" 1206 2.2,37.139 r90 top value=1.00Meg
R4 "RC1206FR-071ML" 1206 2.2,32.075 r90 top value=1.00Meg
R5 "RC0603FR-0742R2L" 0603 39,38.075 r0 top value=1.00
R6 "RC0603FR-0742R2L" 0603 37.35,54.975 r0 top value=1.00
R7 "RC0603FR-071RL" 0603 37.35,56.55 r0 top value=1.00
R8 "RC0603FR-071RL" 0603 39.025,39.725 r0 top value=1.00
R9 "RC0603FR-0751KL" 0603 37.35,58.125 r0 top value=51.0k
R10 "RC0603FR-0751KL" 0603 41.4,38.925 r90 top value=51.0k
R11 "RC0603FR-07240RL" 0603 39.425,24.657 r0 top value=240
R12 "CRCW12060000Z0EA" 1206 78.85,28.1 r180 bottom value=0
R13 "RC0603FR-071K24L" 0603 77.875,9.15 r90 bottom value=1.24k
R14 "CRCW12064R70JNEA" 1206 82.675,43.65 r90 bottom value=4.7
R15 "RC0603FR-071K24L" 0603 77.875,12.975 r270 bottom value=1.24k
R16 "MCR03EZPJ000" 0603 84.575,7.213 r90 bottom value=0
R17 "CRCW06030000Z0EA" 0603 100.637,14.316 r90 bottom value=0
R18 "CRCW06031K21FKEA" 0603 103.125,16.725 r0 bottom value=1.21k
R19 "RC0603FR-075K11L" 0603 103.15,15.125 r0 bottom value=5.11k
R20 "CRCW06034K99FKEA" 0603 98.825,15.866 r90 bottom value=4.99k
R21 "RCG060310K0FKEA" 0603 98.825,12.55 r90 bottom value=10.0k
R22 "RC1206FR-0710RL" 1206 116.576,27.825 r180 bottom value=10.0
R24 "RC1206FR-0710RL" 1206 116.525,63.34 r180 bottom value=10.0
R25 "CRCW060333K2FKEA" 0603 107.45,6.425 r270 bottom value=33.2k
R26 "RC0603FR-071KL" 0603 109.31,9.85 r90 bottom value=1.00k
R27 "RC0603FR-07137KL" 0603 110.109,7.325 r0 bottom value=137k
R28 "RC0603FR-077K5L" 0603 107.45,9.95 r270 bottom value=7.50k
R29 "CRCW06030000Z0EA" 0603 115.625,3.725 r0 bottom value=20.0
R101 "CRCW12063M24FKEA" 1206 8.75,58.45 r90 bottom value=3.24Meg
R102 "RC0603FR-071M5L" 0603 9.329,41.725 r270 bottom value=1.50Meg
R103 "CRCW06031K00JNEA" 0603 14.5,44.4 r180 bottom value=1.0k
R104 "RC0603FR-071ML" 0603 10.4,51.175 r270 bottom value=1.00Meg
R105 "RC0603FR-071ML" 0603 13.35,46.3 r180 bottom value=1.00Meg
R106 "RC0603FR-07220RL" 0603 9.825,48.025 r0 bottom value=220
R107 "CRCW060310K0JNEA" 0603 71.85,16.4 r270 bottom value=10k
R108 "ERJ-3GEY0R00V" 0603 71.85,20.45 r90 bottom value=0
R109 "ERJ-3GEY0R00V" 0603 28.594,16.632 r90 top value=0
R110 "ERJ-3RQF2R2V" 0603 25.45,29.175 r180 bottom value=2.20
R111 "CRCW12062M43FKEA" 1206 21.65,11.055 r90 top value=2.43Meg
R112 "CRCW12062M43FKEA" 1206 25.475,9.325 r180 top value=2.43Meg
R113 "CRCW12062M43FKEA" 1206 30.5,9.35 r180 top value=2.43Meg
R114 "CRCW060336K0JNEA" 0603 31.7,11.95 r0 top value=36k
R115 "RC0603FR-07590KL" 0603 41.1,13.1 r270 top value=590k
R116 "RC0603FR-0771K5L" 0603 39.525,13.1 r90 top value=71.5k
R117 "RC0603FR-07604KL" 0603 41.1,9.85 r90 top value=604k
R118 "RC0603FR-07165KL" 0603 39.525,9.85 r270 top value=165k
R119 "RG1608P-153-B-T5" 0603 34.763,7.15 r180 top value=15.0k
R120 "RG1608P-153-B-T5" 0603 40.189,5.175 r0 top value=15.0k
R121 "B57371V2474J060" FP-B57371V2474J060_0603-MFG 53.1,6.4 r180 top value=470k
R122 "ERJ-3RQF2R2V" 0603 34.475,38.05 r90 top value=2.20
R123 "CRCW12062M43FKEA" 1206 21.67,21.233 r90 top value=2.43Meg
R124 "CRCW12062M43FKEA" 1206 21.67,16.157 r90 top value=2.43Meg
R125 "CRCW12063M24FKEA" 1206 10.45,62.75 r0 bottom value=3.24Meg
R126 "RC0603FR-07715KL" 0603 12.325,37.2 r0 bottom value=715k
R127 "CRCW12063M24FKEA" 1206 13.4,60.112 r0 bottom value=3.24Meg
R128 "ERJ-8GEY0R00V" 1206 25.625,17.275 r270 top value=0
R129 "RC0603FR-07200KL" 0603 32.35,26.025 r0 bottom value=200k
SGND "5011" Keystone5011 147.15,26.65 r90 top
SGND2 "5011" Keystone5011 100.625,2.65 r90 top
SW "5012" Keystone5012#1 73.629,70.02 r0 top
T1 "750345697" "Transformer 750345697" 88.922,48.879 r0 top locked
U1 "ATL432LIAIDBZR" DBZ0003A_N 104.625,10.3 r90 bottom
U101 "UCC256602DDBR" DDB0014A-MFG 34.598,18.557 r90 top
U102 "UCC5350MCQDRQ1" D0008A-MFG 32.1,55.75 r0 top locked
VAUX "5010" Keystone5010 84.1,28.3 r90 top
VCC "5010" Keystone5010 83.85,20.025 r0 top
Vin "5010" Keystone5010 2.125,66.775 r0 top locked
Vout "5010" Keystone5010 146.95,46.475 r90 top

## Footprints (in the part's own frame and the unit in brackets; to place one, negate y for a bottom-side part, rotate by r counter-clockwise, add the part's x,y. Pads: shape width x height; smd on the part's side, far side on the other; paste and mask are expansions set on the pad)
3M_961102-68 [mm] "Header, 2.54mm, 2x1, TH"
  rrect50% 1.5x1.5 hole 1: 1(-1.27,0)
  round 1.5 hole 1: 2(1.27,0)
  silkscreen extent -2.8,-1.25 2.54,1.25, body extent -2.54,-1.25 2.54,1.25, height 9.3
0603 [mm] "0603 from SM-752 data"
  rect 1x0.95 smd: 1(-0.8,0) 2(0.8,0)
  silkscreen extent -1.52,-0.69 1.52,0.69, body extent -0.87,-0.47 0.87,0.47, height 1
0805 [mm] "0805 from SM-752 data"
  rect 1.3x1.5 smd: 1(-0.85,0) 2(0.85,0)
  silkscreen extent -1.72,-0.97 1.72,0.97, body extent -1.1,-0.72 1.1,0.72, height 1.45
0805_HV [mil] "0805 with 30mil clearance between pads"
  rect 50x63 smd: 1(-40,0) 2(40,0)
  silkscreen extent -74,-40 74,40, body extent -43,-29 43,29, height 57
1206 [mm] "1206 from SM-752 data"
  rect 1.3x1.85 smd: 1(-1.45,0) 2(1.45,0)
  silkscreen extent -2.4,-1.21 2.4,1.21, body extent -1.7,-0.9 1.7,0.9, height 1.35
531202 [mm] "TH, 2-Leads, Body 34.92x12.7mm, Pin Spacing 25.4mm"
  round 4 hole 2.67: 1(-12.7,0) 2(12.7,0)
  silkscreen extent -17.46,-6.35 17.46,6.35, body extent -17.46,-6.35 17.46,6.35, height 50.8
691111710002 [mm] "5,00mm - modular - green - Horizontal entry with pressure clamp - 10,0mm height - 02p"
  rrect50% 2.5x2.5 hole 1.6: 1(-2.5,0)
  round 2.5 hole 1.6: 2(2.5,0)
  silkscreen extent -5.6,-4 5.6,4, body extent -5.6,-4 5.6,4, height 11.05
B81123_2650x850x1650 [mm] "TH, 2-Leads, Body 26.5x8.5mm, Lead Spacing 22.5mm"
  round 2 hole 1.2: 1(-11.25,0) 2(11.25,0)
  silkscreen extent -13.25,-4.25 13.25,4.25, body extent -13.25,-4.25 13.25,4.25, height 16.5
Bumpon_SJ5003Transparent [mil] "3M Hemispherical Bumpon transparent"
  round 1 on Mech3: 0(0,0)
  silkscreen extent -228,-228 228,228, body extent -217,-218 219,218, height 197
CE_Mark_5mm [mm] "Minimum text height for CE Mark"
  silkscreen extent -3.5,-2.5 3.5,2.5
D0008A-MFG [mm]
  rrect17% 1.55x0.6 smd paste+0 mask+0: 1(-2.7,1.905) 2(-2.7,0.635) 3(-2.7,-0.635) 4(-2.7,-1.905) 5(2.7,-1.905) 6(2.7,-0.635) 7(2.7,0.635) 8(2.7,1.905)
  silkscreen extent -4.17,-2.5 1.5,2.5, body extent -3,-2.45 3,2.45, height 1.75
DBZ0003A_N [mm] "SOT23, 3-Leads, Body 2.9x1.3mm, Pitch 0.95mm, Lead Span 2.4mm, IPC Medium Density"
  rrect17% 1x0.6 smd: 1(-1.2,0.95) 2(-1.2,-0.95) 3(1.2,0)
  silkscreen extent 0.2,-1.5 0.7,1.5, body extent -1.26,-1.46 1.26,1.46, height 0.98
DDB0014A-MFG [mm]
  rrect17% 1.55x0.6 smd paste+0 mask+0: 1(-2.7,4.445) 3(-2.7,1.905) 4(-2.7,0.635) 5(-2.7,-0.635) 6(-2.7,-1.905) 7(-2.7,-3.175) 8(-2.7,-4.445) 9(2.7,-4.445) 10(2.7,-3.175) 11(2.7,-1.905) 12(2.7,-0.635) 14(2.7,1.905) 15(2.7,3.175) 16(2.7,4.445)
  silkscreen extent -4.12,-5 2,5, body extent -3.01,-4.95 3.01,4.95, height 1.75
DE1_800x700x1100 [mm] "TH, 2-Leads, Dia 8mm, Lead Spacing 10mm"
  round 2 hole 1.2: 1(-5,0) 2(5,0)
  silkscreen extent -4,-3.15 4,3.15, body extent -5.35,-3.5 5.35,3.5, height 11
DFS0004A-MFG [mm]
  rrect33% 1.3x0.6 smd paste+0 mask+0: 1(-4.733,1.25) 2(-4.733,-1.25) 3(4.733,-1.25) 4(4.733,1.25)
  silkscreen extent -6.08,-1.85 3.5,1.85, body extent -5.15,-1.8 5.15,1.8, height 2.6
FCC_disclaimer [mm]
FP-B57371V2474J060_0603-MFG [mm]
  rrect10% 1x1 smd paste+0 mask+0: 1(-1,0) 2(1,0)
  silkscreen extent -0.13,-0.48 0.13,0.48, body extent -0.8,-0.4 0.8,0.4, height 0.9
FP-IMBG120R026M2HXTMA1_TO263-7-MFG [mm] "Recommended Land Pattern"
  rrect13% 0.8x4.7 smd paste-1000 mask+0: 1(-3.81,-7.825) 2(-2.54,-7.825) 3(-1.27,-7.825) 4(0,-7.825) 5(1.27,-7.825) 7(3.81,-7.825) ""(2.54,-7.825)
  rrect1% 10.8x7.1 smd paste-1000 mask+0: 8(0,2.875)
  silkscreen extent -5.1,-10.03 5.1,-1.05, body extent -5.5,-10.28 5.5,6.53, height 0.25
FP-MBR30200CTE3_TU_TO220-3-MFG [mm]
  rrect5% 2.6x2.05 hole 1.35 paste-1000 mask+0: 1(-0.514,2.54)
  oval 2.6x2.05 hole 1.35 paste-1000 mask+0: 2(-0.514,0) 3(-0.514,-2.54)
  silkscreen extent -2.49,-5.32 2.49,5.95, body extent -2.59,-5.42 2.59,5.42, height 0.25
FP-PBHV8560Z_SOT-223-IPC_B [mm]
  rrect11% 2.104x0.872 smd paste+0 mask+0: 1(-2.95,2.3)
  rrect100% 2.104x0.872 smd paste+0 mask+0: 2(-2.95,0) 3(-2.95,-2.3)
  rrect41% 2.104x3.172 smd paste+0 mask+0: 4(2.95,0)
  silkscreen extent -3.08,-3.25 1.2,3.62, body extent -4.25,-3.5 4.25,3.5, height 0.25
IEC_HighVoltage_Small [mm]
  silkscreen extent -2.72,-2.24 2.72,2.47
IEC_HotSurface_Small [mm]
  silkscreen extent -2.72,-2.36 2.72,2.35
"Inductor 750345698" [mm]
  round 1 on Top Overlay: 1(-10.147,10.122) 6(-10.147,-10.122)
  round 2.6 hole 1.8: 2(-10.147,6.312) 3(-10.147,2.502) 4(-10.147,-2.502) 5(-10.147,-6.312) 10(10.147,-2.502) 11(10.147,2.502)
  silkscreen extent -11.99,-12.15 12.01,11.96
Keystone5010 [mm] "Keystone Multipurpose loops"
  round 2.6 hole 1.6: 1(0,0)
  silkscreen extent -1.78,-1.78 1.78,1.78, body extent -1.59,-1.61 1.58,1.59, height 8.09
Keystone5011 [mm] "Keystone Multipurpose loops"
  round 2.6 hole 1.6: 1(0,0)
  silkscreen extent -1.78,-1.78 1.78,1.78, body extent -1.6,-1.6 1.59,1.59, height 8.1
Keystone5012#1 [mm] "Keystone Multipurpose loops"
  round 2.6 hole 1.6: 1(0,0)
  silkscreen extent -1.78,-1.78 1.78,1.78, body extent -1.59,-1.61 1.58,1.59, height 8.09
Keystone5012#2 [mm] "Keystone Multipurpose loops"
  round 2.21 hole 1.6: 1(0,0)
  silkscreen extent -1.78,-1.78 1.78,1.78, body extent -1.6,-1.6 1.59,1.59, height 8.1
Keystone5013 [mm] "Keystone Multipurpose loops"
  round 2.6 hole 1.6: 1(0,0)
  silkscreen extent -1.78,-1.78 1.78,1.78, body extent -1.6,-1.6 1.59,1.59, height 8.1
Keystone_1902C [mil] "Hex Standoff, 4-40 threaded, nylon"
  round 1 on Mech3: 0(0,0)
  body extent -145,-126 146,126, height 501
M_800x1150#1 [mm] "TH, 2-Leads, Dia 8mm, Pin Spacing 3.5mm"
  rect 2x2 hole 1.2: 1(-1.75,0)
  round 2 hole 1.2: 2(1.75,0)
  silkscreen extent -4.25,-4.25 4.25,4.25, body extent -4.22,-4.24 4.24,4.24, height 12.51
M_800x1150#2 [mm] "TH, 2-Leads, Dia 8mm, Pin Spacing 3.5mm"
  rect 1.8x2.4 hole 1.2: 1(-1.75,0)
  oval 1.8x2.4 hole 1.2: 2(1.75,0)
  silkscreen extent -4.25,-4.25 4.25,4.25, body extent -4.22,-4.24 4.24,4.24, height 12.51
"NY PMS 440 0025 PH" [mm] "4-40 nylon screw and mounting hole"
  round 8 hole 3.2: 1(0,0)
  body extent -3.3,-3.3 3.3,3.3, height 2.69
PJ_800X1500 [mm] "TH, 2-Leads, Dia 8mm, Lead Spacing 3.5mm"
  rect 1.35x1.35 hole 0.85: 1(-1.75,0)
  round 1.35 hole 0.85: 2(1.75,0)
  silkscreen extent -4.25,-4.25 4.25,4.25, body extent -4.22,-4.24 4.24,4.24, height 16.51
SMA [mm] "Molded Diode, 2-Leads, Body 4.3x2.6mm, IPC Medium Density, based on OnSemi component dimensions and land pattern"
  rect 2x2 smd: 1(-2,0) 2(2,0)
  silkscreen extent -3.66,-1.58 2.79,1.57, body extent -2.6,-1.3 2.6,1.3, height 2.42
SMAF [mm] "SMD, 2-Leads, Body 3.8x2.5mm"
  rect 1.24x1.89 smd: 1(-2.04,0) 2(2.04,0)
  silkscreen extent -3.4,-1.3 2.8,1.3, body extent -2.35,-1.25 2.35,1.25
SMB [mm] "Molded Diode, 2-Leads, Body 5.4x3.6mm, IPC Medium Density, based on OnSemi component dimensions"
  rect 2.159x2.743 smd: 1(-2.21,0) 2(2.21,0)
  silkscreen extent -3.94,-2.08 3.18,2.08, body extent -2.7,-1.8 2.7,1.8, height 2.32
SOD-123 [mm] "On Semi recommended land pattern"
  rect 0.915x1.22 smd: 1(-1.637,0) 2(1.637,0)
  silkscreen extent -2.74,-1.17 2.03,1.17, body extent -1.93,-0.9 1.93,0.9, height 1.35
SOD-123W [mm] "NXP recommended land pattern"
  rect 1.2x1.2 smd paste-0.05: 1(-1.4,0) 2(1.4,0)
  silkscreen extent -2.64,-1.14 1.68,1.14, body extent -1.85,-0.95 1.85,0.95, height 1.1
SOD-323 [mm] "NXP recommended land pattern"
  rect 0.6x0.6 smd paste-0.05: 1(-1.1,0) 2(1.1,0)
  silkscreen extent -2.06,-0.86 1.53,0.86, body extent -1.3,-0.67 1.3,0.68, height 1.1
SOT-23 [mm] "SOT23, 3-Leads, Body 2.9x1.3mm, Pitch 0.95mm, Lead Span 2.5mm, IPC Medium Density"
  rrect50% 1x0.6 smd: 1(-1.2,0.95) 2(-1.2,-0.95) 3(1.2,0)
  silkscreen extent -1.62,-1.5 0.7,1.5, body extent -1.16,-1.45 1.21,1.45, height 1
SOT-223 [mm] "SOT223/SC73, 4-Leads, Body 6.5x3.5mm, Pitch 2.3mm, Lead Span 7mm, IPC Medium Density"
  rrect10% 2.4x1 smd: 1(-2.9,2.3) 2(-2.9,0) 3(-2.9,-2.3)
  rrect4% 2.4x3.3 smd: 4(2.9,0)
  silkscreen extent -3.32,-3.35 1.4,3.35, body extent -3.5,-3.25 3.5,3.25, height 1.62
SOT-323 [mm] "Diodes Inc recommended land pattern.  2016-02-24"
  rrect21% 0.6x0.47 smd: 1(-0.95,0.65) 2(-0.95,-0.65) 3(0.95,0)
  silkscreen extent -1.14,-1.22 0.77,1.22, body extent -1.13,-1.13 1.12,1.12, height 1.13
SOT-363 [mm]
  rect 0.6x0.4 smd mask+0.051: 1(-0.95,0.65) 2(-0.95,0) 3(-0.95,-0.65) 4(0.95,-0.65) 5(0.95,0) 6(0.95,0.65)
  silkscreen extent -0.38,-1.02 0.38,1.02, body extent -1.1,-1.1 1.1,1.1, height 1.12
TI_Stacked_Overlay_Small [mm]
  silkscreen extent -10.63,-2.49 10.63,2.49
"Transformer 750345697" [mm]
  round 3 hole 1.8: 1(-15.303,13.957) 2(-15.303,8.852) 3(-15.303,3.746) 4(-15.303,-3.746) 5(-15.303,-8.852) 6(-15.303,-13.957) 7(15.303,-13.957) 8(15.303,-8.852) 9(15.303,-3.746) 10(15.303,3.746) 11(15.303,8.852) 12(15.303,13.957)
  silkscreen extent -19.05,-17.78 19.05,17.78
UCY_1250x3550 [mm] "Nichicon"
  rect 2x2 hole 1.2: 1(-2.5,0)
  round 2 hole 1.2: 2(2.5,0)
  silkscreen extent -6.55,-6.55 6.55,6.55, body extent -6.5,-6.5 6.51,6.5, height 37.01
UCZ_1250x1350 [mm] "SMD, 2-Leads, Dia 12.5mm"
  rect 2x2 smd: 1(-6.3,0) 2(6.3,0)
  Top Layer region: 8.8,-3.5 8.8,3.5 3.8,3.5 3.8,1 1.5,1 1.5,-1 3.8,-1 3.8,-3.5
  Top Layer region: -8.8,-3.5 -8.8,3.5 -3.8,3.5 -3.8,1 -1.5,1 -1.5,-1 -3.8,-1 -3.8,-3.5
  silkscreen extent -6.9,-6.9 6.9,6.9, body extent -6.9,-6.9 6.9,6.9, height 14.51
WEEE_Minimum [mm] "WEEElie bin"
  silkscreen extent -2.42,-4.38 2.52,2.65

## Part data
5VP VAUX VCC Vin Vout: library part CMP-0055147-2, "Test Point, Multipurpose, Red, TH", Color=Red, Manufacturer="Keystone Electronics", Supplier Part Number 1=36-5010-ND
BLK HG I_opt ISNS LG OVP_OTP SW: library part CMP-0055149-2, "Test Point, Multipurpose, White, TH", Color=White, Manufacturer="Keystone Electronics", Supplier Part Number 1=36-5012-ND
C1 C2: library part CMP-0010255-2, "CAP, AL, 22 uF, 500 V, +/- 20%, TH", Cap_Case=12.5x35.5mm, Manufacturer=Nichicon, Supplier Part Number 1=493-6916-ND, Tolerance_%=20%, Value1=Unknown, Value2=500V, ValueDisplayed=22uF
C3 C4: library part CMP-0012464-3, "CAP, Film, 6800 pF, 3000 V, +/- 20%, TH", Cap_Case=26.5x8.5x16.5mm, Manufacturer=TDK, Supplier Part Number 1=495-1654-ND, Tolerance_%=20%, Value1=Unknown, Value2=3000V, ValueDisplayed=6800pF
C5 C6: library part CMP-0009030-2, "CAP, CERM, 100 pF, 1000 V, +/- 5%, C0G/NP0, 1206", Cap_Case=1206, Manufacturer=Vishay-Vitramon, Supplier Part Number 1=720-1011-1-ND, TempCo=C0G/NP0, Tolerance_%=5%, Value1=Unknown, Value2=1000V, ValueDisplayed=100pF
C7: library part CMP-0006894-1, "CAP, CERM, 220 pF, 50 V, +/- 10%, C0G/NP0, 0603", Cap_Case=0603, Manufacturer=Kemet, Supplier Part Number 1=399-1065-1-ND, TempCo=C0G/NP0, Tolerance_%=10%, Value1=Unknown, Value2=50V, ValueDisplayed=220pF
C8: library part CMP-0007883-2, "CAP, CERM, 2.2 uF, 35 V, +/- 10%, X7R, 0805", Cap_Case=0805, Manufacturer=TDK, Supplier Part Number 1=445-14547-1-ND, TempCo=X7R, Tolerance_%=10%, Value1=Unknown, Value2=35V, ValueDisplayed=2.2uF
C9: library part CMP-0007450-1, "CAP, CERM, 3300 pF, 50 V, +/- 10%, X7R, 0603", Cap_Case=0603, Manufacturer=MuRata, Supplier Part Number 1=490-1503-1-ND, TempCo=X7R, Tolerance_%=10%, Value1=Unknown, Value2=50V, ValueDisplayed=3300pF
C10: library part CMP-0082252-1, "CAP, CERM, 10 µF, 25 V,+/- 20%, X7R, AEC-Q200 Grade 1, 1206", Cap_Case=1206, Manufacturer=MuRata, Supplier Part Number 1=490-6519-1-ND, TempCo=X7R, Tolerance_%=20%, Value2=25V, ValueDisplayed=10µF
C11 C115: library part CMP-0010327-2, "CAP, AL, 220 uF, 35 V, +/- 20%, TH", Cap_Case=8x11.5mm, Manufacturer=Panasonic, Supplier Part Number 1=P10419TB-ND, Tolerance_%=20%, Value1=Unknown, Value2=35V, ValueDisplayed=220uF
C12: library part CMP-0006841-4, "CAP, CERM, 100 pF, 50 V, +/- 5%, C0G/NP0, 0603", Cap_Case=0603, Manufacturer=Kemet, Supplier Part Number 1=399-1061-1-ND, TempCo=C0G/NP0, Tolerance_%=5%, Value1=Unknown, Value2=50V, ValueDisplayed=100pF
C13: library part CMP-0079247-1, "CAP, CERM, 4700 pF, 100 V,+/- 10%, X7R, AEC-Q200 Grade 1, 0603", Cap_Case=0603, Manufacturer=MuRata, Supplier Part Number 1=490-4930-1-ND, TempCo=X7R, Tolerance_%=10%, Value2=100V, ValueDisplayed=4700pF
C14 C16: library part CMP-0008122-2, "CAP, CERM, 470 pF, 100 V, +/- 5%, C0G/NP0, 0805", Cap_Case=0805, Manufacturer=MuRata, Supplier Part Number 1=490-1611-1-ND, TempCo=C0G/NP0, Tolerance_%=5%, Value1=Unknown, Value2=100V, ValueDisplayed=470pF
C15 C105: library part CMP-0007433-1, "CAP, CERM, 0.01 uF, 50 V, +/- 10%, X7R, 0603", Cap_Case=0603, Manufacturer=MuRata, Supplier Part Number 1=490-1512-1-ND, TempCo=X7R, Tolerance_%=10%, Value1=Unknown, Value2=50V, ValueDisplayed=0.01uF
C17: library part CMP-0007185-4, "CAP, CERM, 150 pF, 50 V, +/- 5%, C0G/NP0, 0603", Cap_Case=0603, Manufacturer=MuRata, Supplier Part Number 1=490-1431-1-ND, TempCo=C0G/NP0, Tolerance_%=5%, Value1=Unknown, Value2=50V, ValueDisplayed=150pF
C18 C20: library part CMP-0011410-2, "CAP, AL HYBRID, 180 uF, 63 V, +/- 20%, 0.015 ohm, SMD", Cap_Case=12.5x13.5mm, Manufacturer=Nichicon, PartNumber=UCZ1J181MNQ1MS, Supplier Part Number 1=493-13950-1-ND, Tolerance_%=20%, Value1="0.2 ohm", Value2=63V, ValueDisplayed=180uF
C19: library part CMP-0007482-4, "CAP, CERM, 470 pF, 100 V, +/- 10%, X7R, 0603", Cap_Case=0603, Manufacturer=MuRata, Supplier Part Number 1=490-1467-1-ND, TempCo=X7R, Tolerance_%=10%, Value1=Unknown, Value2=100V, ValueDisplayed=470pF
C21 C22: library part CMP-0009929-2, "CAP, AL, 47 uF, 80 V, +/- 20%, TH", Cap_Case=8x15mm, Manufacturer=Nichicon, Supplier Part Number 1=493-11811-1-ND, Tolerance_%=20%, Value1=Unknown, Value2=80V, ValueDisplayed=47uF
C23 C24: library part CMP-0007895-2, "CAP, CERM, 0.47 uF, 100 V, +/- 10%, X7S, 0805", Cap_Case=0805, Manufacturer=TDK, Supplier Part Number 1=445-5203-1-ND, TempCo=X7S, Tolerance_%=10%, Value1="0.017152 ohm", Value2=100V, ValueDisplayed=0.47uF
C25 C26 C27 C28: library part CMP-0009052-2, "CAP, CERM, 0.022 uF, 1000 V, +/- 10%, X7R, 1206", Cap_Case=1206, Manufacturer=Vishay-Vitramon, Supplier Part Number 1=720-1028-1-ND, TempCo=X7R, Tolerance_%=10%, Value1=Unknown, Value2=1000V, ValueDisplayed=0.022uF
C29: library part CMP-0079602-1, "CAP, CERM, 0.1 µF, 50 V,+/- 10%, X7R, AEC-Q200 Grade 1, 0603", Cap_Case=0603, Manufacturer=Kemet, Supplier Part Number 1=399-6856-1-ND, TempCo=X7R, Tolerance_%=10%, Value2=50V, ValueDisplayed=0.1µF
C101: library part CMP-0009029-1, "CAP, CERM, 10 pF, 1000 V, +/- 5%, C0G/NP0, 1206", Cap_Case=1206, Manufacturer=Vishay-Vitramon, Supplier Part Number 1=720-1010-1-ND, TempCo=C0G/NP0, Tolerance_%=5%, Value1=Unknown, Value2=1000V, ValueDisplayed=10pF
C102: library part CMP-0007355-2, "CAP, CERM, 10 uF, 35 V, +/- 20%, X5R, 0603", Cap_Case=0603, Manufacturer=Nichicon, TempCo=X5R, Tolerance_%=20%, Value1=Unknown, Value2=35V, ValueDisplayed=10uF
C103 C104 C116: library part CMP-0076705-3, "CAP, CERM, 1 µF, 25 V,+/- 10%, X7R, AEC-Q200 Grade 1, 0603", Cap_Case=1.6x0.8x0.8mm, Manufacturer=TDK, Supplier Part Number 1=445-6931-1-ND, TempCo=X7R, Tolerance_%=10%, Value2=25V, ValueDisplayed=1µF
C106: library part CMP-0006982-4, "CAP, CERM, 220 pF, 50 V, +/- 10%, X7R, 0603", Cap_Case=0603, Manufacturer=Kemet, Supplier Part Number 1=399-5342-1-ND, TempCo=X7R, Tolerance_%=10%, Value1=Unknown, Value2=50V, ValueDisplayed=220pF
C107 C114: library part CMP-0006861-2, "CAP, CERM, 0.1 uF, 50 V, +/- 10%, X7R, 0603", Cap_Case=0603, Manufacturer=Kemet, Supplier Part Number 1=399-5089-1-ND, TempCo=X7R, Tolerance_%=10%, Value1=Unknown, Value2=50V, ValueDisplayed=0.1uF
C108: library part CMP-0008346-1, "CAP, CERM, 4.7 uF, 25 V, +/- 10%, X7R, 0805", Cap_Case=0805, Manufacturer=MuRata, Supplier Part Number 1=490-9962-1-ND, TempCo=X7R, Tolerance_%=10%, Value1=Unknown, Value2=25V, ValueDisplayed=4.7uF
C109: library part CMP-0006976-5, "CAP, CERM, 1000 pF, 50 V, +/- 10%, X7R, 0603", Cap_Case=0603, Manufacturer=Kemet, Supplier Part Number 1=399-5348-1-ND, TempCo=X7R, Tolerance_%=10%, Value1=Unknown, Value2=50V, ValueDisplayed=1000pF
C110: library part CMP-0006983-4, "CAP, CERM, 2200 pF, 50 V, +/- 10%, X7R, 0603", Cap_Case=0603, Manufacturer=Kemet, Supplier Part Number 1=399-5341-1-ND, TempCo=X7R, Tolerance_%=10%, Value1=Unknown, Value2=50V, ValueDisplayed=2200pF
C111: library part CMP-0084679-1, "CAP, CERM, 0.1 µF, 25 V,+/- 10%, X7R, AEC-Q200 Grade 1, 0603", Cap_Case=0603, Manufacturer=MuRata, TempCo=X7R, Tolerance_%=10%, Value2=25V, ValueDisplayed=0.1µF
C112 C113: library part CMP-0008902-1, "CAP, CERM, 68 pF, 1000 V, +/- 5%, U2J, 1206", Cap_Case=1206, Manufacturer=MuRata, Supplier Part Number 1=490-4300-1-ND, TempCo=U2J, Tolerance_%=5%, Value1=Unknown, Value2=1000V, ValueDisplayed=68pF
CY1: library part CMP-0077649-1, "CAP, CERM, 220 pF,  V,+/- 10%, B, D8xT7mm", Cap_Case=8x7x11mm, Manufacturer=MuRata, Supplier Part Number 1=490-9360-ND, TempCo=B, Tolerance_%=10%, ValueDisplayed=220pF
D1: library part CMP-0079597-1, "Diode, Switching, 75 V, 0.15 A, AEC-Q101, SOD-323", Manufacturer="Diodes Inc.", Supplier Part Number 1=1N4148WS-FDICT-ND, Value1=0.15A, Value2=1.25V
D2: library part CMP-0028977-2, "Diode, Schottky, 100 V, 2 A, AEC-Q101, SOD-123W", Manufacturer=Nexperia, Value1=2A, Value2=0.83V
D3 D4: library part CMP-0089434-2, "Common Cathode Schottky 150V 30A Through Hole TO-220-3", Digikey Part Number=MBR30200CTE3/TU-ND, Forward Current=30A, Manufacturer=Microsemi, Max Surge Forward Current=275A, Mouser Part Number=494-MBR30200CTE3/TU, Operating Temperature Range="-65°C to +175°C", Part Number=MBR30200CTE3/TU, Peak Reverse Current=0.05mA
D5 D105 D106 D107: library part CMP-0085765-1, "Diode, Zener, 18 V, 300 mW, AEC-Q101, SOD-323", Manufacturer="ON Semiconductor", Power_W=300mW, Value1=0.3W
D101 D102 D103 D104: library part CMP-0005620-4, "Diode, Zener, 130 V, 550 mW, SMB", Manufacturer="ON Semiconductor", Power_W=550mW, Value1=0.55W
D108: library part CMP-0076908-2, "Diode, Ultrafast, 600 V, 1 A, SMA", Manufacturer=STMicroelectronics, Value1=1A, Value2=1V
D109: library part CMP-0085157-1, "Diode, Zener, 26 V, 500 mW, AEC-Q101, SOD-123", Manufacturer="Diodes Inc.", Power_W=500mW, Value1=0.5W
D110 D111: library part CMP-0029162-2, "Diode, Ultrafast, 600 V, 1 A, AEC-Q101, SMAF", Manufacturer="Fairchild Semiconductor", Value1=1A, Value2=1.7V
D112: library part CMP-0077081-1, "Diode, Ultrafast, 1200 V, 1 A, SMA", Manufacturer=STMicroelectronics, Supplier Part Number 1=497-8048-1-ND, Value1=1A, Value2=1.9V
D113: library part CMP-0028802-1, "Diode, Schottky, 40 V, 1 A, SOD-323", Manufacturer="Torex USA Corporation", Supplier Part Number 1=893-1188-1-ND, Value1=1A, Value2=0.54V
D114: library part CMP-0085757-1, "Diode, Zener, 12 V, 300 mW, SOD-323", Manufacturer="ON Semiconductor", Power_W=300mW, Value1=0.3W
D115: library part CMP-0085762-1, "Diode, Zener, 15 V, 300 mW, SOD-323", Manufacturer="ON Semiconductor", Power_W=300mW, Value1=0.3W
H1 H2: library part CMP-0004053-1, Manufacturer=Aavid, Supplier Part Number 1=HS382-ND
H201 H204 H207 H210: library part CMP-0003620-1, "Bumpon, Hemisphere, 0.44 X 0.20, Clear", Manufacturer=3M, Supplier Part Number 1=SJ5303-7-ND
H202 H205 H208 H211: library part CMP-0003610-1, "Standoff, Hex, 0.5\"L #4-40 Nylon", Manufacturer=Keystone, Supplier Part Number 1=36-1902C-ND
H203 H206 H209 H212: library part CMP-0003617-1, "Machine Screw, Round, #4-40 x 1/4, Nylon, Philips panhead", Manufacturer="B&F Fastener Supply", Supplier Part Number 1=H542-ND
Inj1 Inj2: library part CMP-0055150-2, "Test Point, Multipurpose, Orange, TH", Color=Orange, Manufacturer="Keystone Electronics", Supplier Part Number 1=36-5013-ND
J1 J2 J5: library part CMP-1502-03262-2, Case/Package=J, Color=Green, Current Rating=8A, Manufacurer="Würth Elektronik", Max Operating Temperature=105°C, Min Operating Temperature=-40°C, Voltage Rating=300V
J3 J4: library part CMP-0075355-1, "Header, 2.54mm, 2x1, Gold, TH", Color=Black, Current_A=2A, Manufacturer=3M, Supplier Part Number 1=3M155862-ND
L1: library part "Inductor 750345698", "Customized resonant inductor; L = 186uH", Manufacturer=Wurth
Logo201: library part CMP-0074838-1, "Texas Instrument Corporate Signature"
Logo202: library part CMP-0074844-1
Logo203: library part CMP-0074847-1, "FCC_disclaimer"
Logo204: library part CMP-0074769-1
LOGO205 LOGO206 LOGO207 LOGO208: library part CMP-0074835-1, "IEC 61010-1 High Voltage Warning"
Logo206: library part CMP-0074837-2, "IEC 61010-1 Hot Surface Warning", Manufacturer="Texas Instruments"
PGND PGND PGND SGND SGND2: library part CMP-0055148-2, "Test Point, Multipurpose, Black, TH", Color=Black, Manufacturer="Keystone Electronics", Supplier Part Number 1=36-5011-ND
